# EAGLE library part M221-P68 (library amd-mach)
AMD MACH SERIES
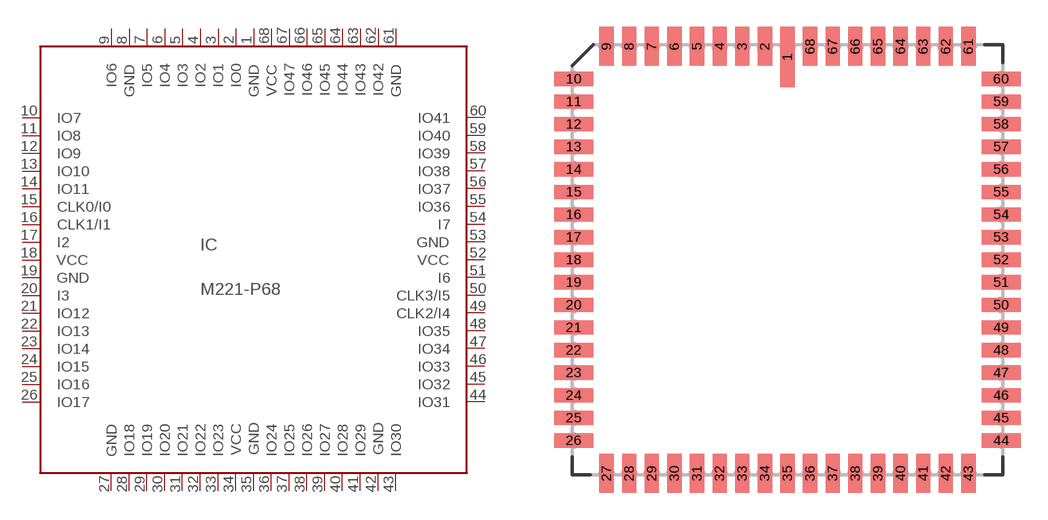
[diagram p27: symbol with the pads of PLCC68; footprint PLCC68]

Designator prefix IC

## M221-P68 (OC_FARNELL: unknown; OC_NEWARK: unknown)  [PLCC68]
1  GND  pwr
2  IO0
3  IO1
4  IO2
5  IO3
6  IO4
7  IO5
8  GND  pwr
9  IO6
10  IO7
11  IO8
12  IO9
13  IO10
14  IO11
15  CLK0/I0  in
16  CLK1/I1  in
17  I2  in
18  VCC  pwr
19  GND  pwr
20  I3  in
21  IO12
22  IO13
23  IO14
24  IO15
25  IO16
26  IO17
27  GND  pwr
28  IO18
29  IO19
30  IO20
31  IO21
32  IO22
33  IO23
34  VCC  pwr
35  GND  pwr
36  IO24
37  IO25
38  IO26
39  IO27
40  IO28
41  IO29
42  GND  pwr
43  IO30
44  IO31
45  IO32
46  IO33
47  IO34
48  IO35
49  CLK2/I4  in
50  CLK3/I5  in
51  I6  in
52  VCC  pwr
53  GND  pwr
54  I7  in
55  IO36
56  IO37
57  IO38
58  IO39
59  IO40
60  IO41
61  GND  pwr
62  IO42
63  IO43
64  IO44
65  IO45
66  IO46
67  IO47
68  VCC  pwr

## Footprint PLCC68 (pad centres in mm)
PLASTIC LEADED CHIP CARRIER
smd 0.8 x 3.4: 1 0,11.4
smd 0.8 x 2.2: 2 -1.27,12; 3 -2.54,12; 4 -3.81,12; 5 -5.08,12; 6 -6.35,12; 7 -7.62,12; 8 -8.89,12; 9 -10.16,12; 27 -10.16,-12; 28 -8.89,-12; 29 -7.62,-12; 30 -6.35,-12; 31 -5.08,-12; 32 -3.81,-12; 33 -2.54,-12; 34 -1.27,-12; 35 0,-12; 36 1.27,-12; 37 2.54,-12; 38 3.81,-12; 39 5.08,-12; 40 6.35,-12; 41 7.62,-12; 42 8.89,-12; 43 10.16,-12; 61 10.16,12; 62 8.89,12; 63 7.62,12; 64 6.35,12; 65 5.08,12; 66 3.81,12; 67 2.54,12; 68 1.27,12
smd 2.2 x 0.8: 10 -12,10.16; 11 -12,8.89; 12 -12,7.62; 13 -12,6.35; 14 -12,5.08; 15 -12,3.81; 16 -12,2.54; 17 -12,1.27; 18 -12,0; 19 -12,-1.27; 20 -12,-2.54; 21 -12,-3.81; 22 -12,-5.08; 23 -12,-6.35; 24 -12,-7.62; 25 -12,-8.89; 26 -12,-10.16; 44 12,-10.16; 45 12,-8.89; 46 12,-7.62; 47 12,-6.35; 48 12,-5.08; 49 12,-3.81; 50 12,-2.54; 51 12,-1.27; 52 12,0; 53 12,1.27; 54 12,2.54; 55 12,3.81; 56 12,5.08; 57 12,6.35; 58 12,7.62; 59 12,8.89; 60 12,10.16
